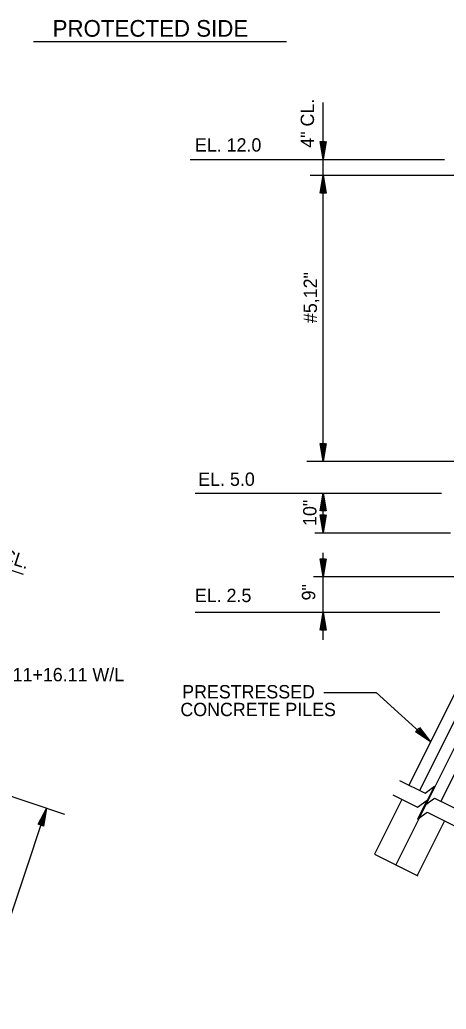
# Model space of a CAD drawing. Extents: x 6 to 106, y 3 to 74.
# Drawn here: x 72.23 to 84.18, y 45.21 to 72.88 of the extents above; entities that cross this region are included whole.
import ezdxf

# ---------------------------------------------------------------- set-up
doc = ezdxf.new("R2010")
doc.units = 0
for name, color, linetype in [('Level 13', 7, 'Continuous'), ('Level 22', 7, 'Continuous'), ('Level 25', 7, 'Continuous'), ('Level 50', 7, 'Continuous')]:
    doc.layers.add(name, color=color, linetype=linetype)

msp = doc.modelspace()

# ---------------------------------------------------------------- linework, layer by layer
at = {"layer": 'Level 13'}
for points in [[(83.581, 51.246), (83.848, 51.448), (83.58, 50.912), (83.848, 51.112)], [(83.374, 50.853), (83.641, 51.054), (83.373, 50.518), (83.641, 50.719)]]:
    msp.add_lwpolyline(points, dxfattribs=at)
at = {"layer": 'Level 22'}
for p, q in [((72.613, 72.269), (79.705, 72.269)), ((80.725, 68.974), (80.725, 70.568)), ((77.003, 68.974), (84.13, 68.974)), ((80.725, 68.53), (80.725, 68.974)), ((80.362, 68.53), (84.509, 68.53)), ((80.725, 60.53), (80.725, 68.53)), ((80.271, 60.53), (84.402, 60.53)), ((77.139, 59.641), (84.039, 59.641)), ((80.725, 58.53), (80.725, 59.641)), ((80.498, 58.53), (84.295, 58.53)), ((86.868, 58.198), (83.43, 51.322)), ((80.725, 57.307), (80.725, 57.968)), ((87.497, 57.965), (84.026, 51.024)), ((86.199, 57.606), (83.131, 51.471)), ((80.453, 57.307), (88.578, 57.307)), ((80.725, 56.307), (80.725, 57.307)), ((77.139, 56.307), (83.994, 56.307)), ((80.725, 55.54), (80.725, 56.307)), ((86.295, 56.307), (82.763, 49.243)), ((80.743, 54.064), (82.217, 54.064)), ((82.217, 54.064), (83.739, 52.686)), ((82.87, 51.601), (83.581, 51.246)), ((82.675, 51.202), (83.374, 50.853)), ((82.933, 51.073), (82.166, 49.541)), ((83.848, 51.112), (84.647, 50.713)), ((83.641, 50.719), (84.392, 50.344)), ((84.125, 50.477), (83.359, 48.944)), ((82.166, 49.541), (83.379, 48.935))]:
    msp.add_line(p, q, dxfattribs=at)
at = {"layer": 'Level 25'}
for p, q in [((72.339, 57.362), (70.827, 57.866)), ((73.495, 50.652), (68.065, 52.462)), ((70.45, 43.235), (72.98, 50.824))]:
    msp.add_line(p, q, dxfattribs=at)
at = {"layer": 'Level 50'}
for p, q in [((80.725, 69.113), (80.725, 69.113)), ((80.725, 68.974), (80.725, 68.974)), ((80.725, 68.53), (80.725, 68.53)), ((80.725, 68.391), (80.725, 68.391)), ((80.725, 60.668), (80.725, 60.668)), ((80.725, 60.53), (80.725, 60.53)), ((80.725, 59.641), (80.725, 59.641)), ((80.725, 59.502), (80.725, 59.502)), ((80.725, 58.668), (80.725, 58.668)), ((80.725, 58.53), (80.725, 58.53)), ((80.725, 57.446), (80.725, 57.446)), ((80.725, 57.307), (80.725, 57.307)), ((80.725, 56.307), (80.725, 56.307)), ((80.725, 56.169), (80.725, 56.169)), ((83.636, 52.779), (83.636, 52.779)), ((83.739, 52.686), (83.739, 52.686)), ((72.936, 50.693), (72.936, 50.693)), ((72.98, 50.824), (72.98, 50.824))]:
    msp.add_line(p, q, dxfattribs=at)
for points in [[(80.808, 69.473), (80.725, 68.974), (80.643, 69.473), (80.784, 69.473), (80.725, 69.113), (80.669, 69.451), (80.76, 69.451), (80.725, 69.246), (80.696, 69.43), (80.733, 69.43), (80.725, 69.385)], [(80.643, 68.031), (80.725, 68.53), (80.808, 68.031), (80.667, 68.031), (80.725, 68.391), (80.781, 68.052), (80.691, 68.052), (80.725, 68.258), (80.755, 68.074), (80.717, 68.074), (80.725, 68.119)], [(80.808, 61.028), (80.725, 60.53), (80.643, 61.028), (80.784, 61.028), (80.725, 60.668), (80.669, 61.007), (80.76, 61.007), (80.725, 60.802), (80.696, 60.986), (80.733, 60.986), (80.725, 60.94)], [(80.643, 59.142), (80.725, 59.641), (80.808, 59.142), (80.667, 59.142), (80.725, 59.502), (80.781, 59.163), (80.691, 59.163), (80.725, 59.369), (80.755, 59.185), (80.717, 59.185), (80.725, 59.23)], [(80.808, 59.028), (80.725, 58.53), (80.643, 59.028), (80.784, 59.028), (80.725, 58.668), (80.669, 59.007), (80.76, 59.007), (80.725, 58.802), (80.696, 58.986), (80.733, 58.986), (80.725, 58.94)], [(80.808, 57.806), (80.725, 57.307), (80.643, 57.806), (80.784, 57.806), (80.725, 57.446), (80.669, 57.785), (80.76, 57.785), (80.725, 57.579), (80.696, 57.763), (80.733, 57.763), (80.725, 57.718)], [(80.643, 55.809), (80.725, 56.307), (80.808, 55.809), (80.667, 55.809), (80.725, 56.169), (80.781, 55.83), (80.691, 55.83), (80.725, 56.035), (80.755, 55.851), (80.717, 55.851), (80.725, 55.897)], [(83.425, 53.082), (83.739, 52.686), (83.314, 52.959), (83.409, 53.064), (83.636, 52.779), (83.347, 52.965), (83.408, 53.032), (83.537, 52.868), (83.381, 52.97), (83.406, 52.998), (83.434, 52.961)], [(72.743, 50.377), (72.98, 50.824), (72.9, 50.325), (72.766, 50.37), (72.936, 50.693), (72.882, 50.354), (72.796, 50.382), (72.894, 50.566), (72.863, 50.382), (72.828, 50.394), (72.85, 50.435)]]:
    msp.add_lwpolyline(points, dxfattribs=at)

# ---------------------------------------------------------------- texts
at = {"layer": 'Level 22'}
for s, height, p in [('PROTECTED SIDE', 0.46667, (73.151, 72.404)), ('EL. 12.0', 0.3733, (77.138, 69.191)), ('EL. 5.0', 0.3733, (77.231, 59.843)), ('EL. 2.5', 0.3733, (77.135, 56.592)), ('STA. 711+16.11 W/L', 0.37333, (70.505, 54.377)), ('PRESTRESSED', 0.37333, (76.78, 53.898)), ('CONCRETE PILES', 0.37333, (76.729, 53.402))]:
    msp.add_text(s, height=height, dxfattribs=at).set_placement(p)
for s, rotation, p in [('4" CL.', 90, (80.472, 69.3)), ('#5,12"', 90, (80.555, 64.395)), ('10"', 90, (80.54, 58.721)), ('3" CL.', 342, (71.127, 57.932)), ('9"', 90, (80.506, 56.639))]:
    msp.add_text(s, height=0.3733, rotation=rotation, dxfattribs=at).set_placement(p)

doc.saveas('drawing.dxf')
